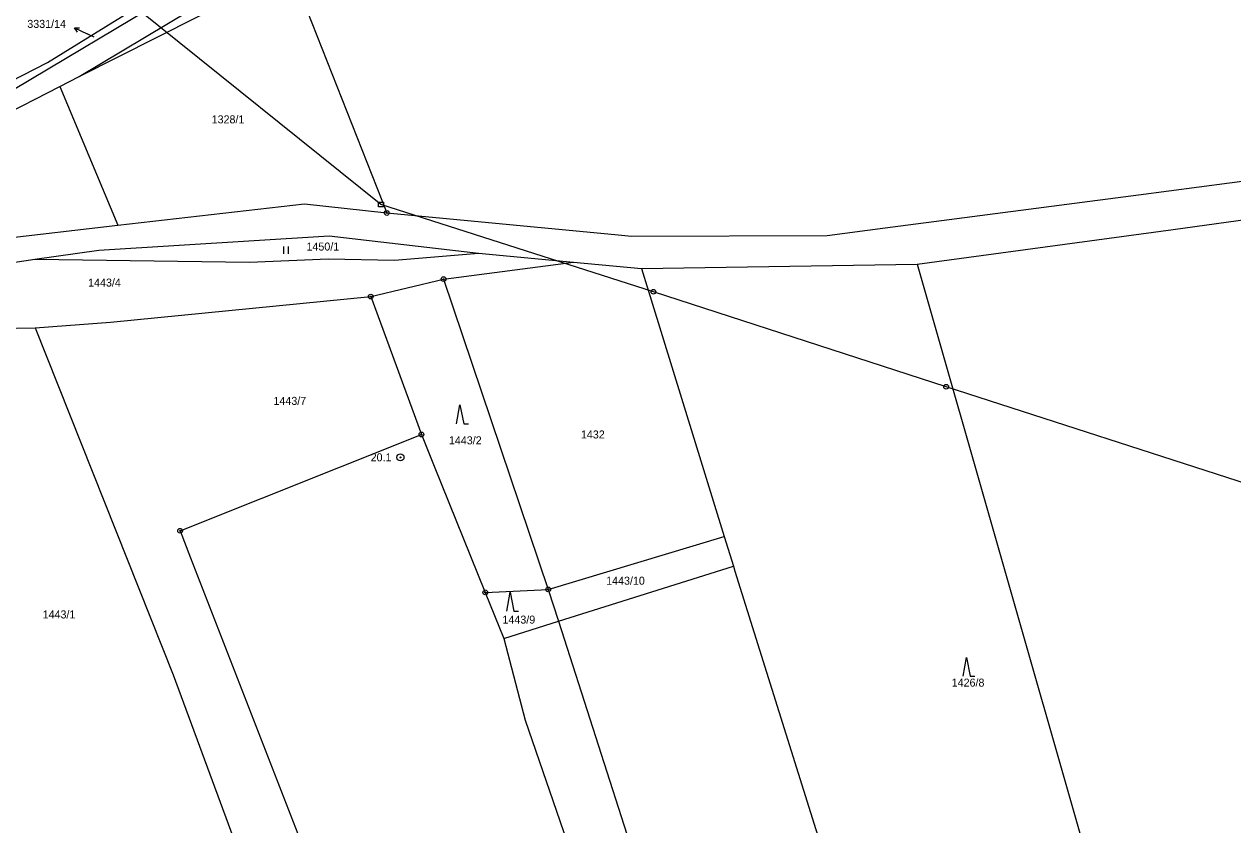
# Model space of a CAD drawing. Extents: x -763205 to -760228, y -1155311 to -1152844.
# Drawn here: x -761010 to -760753.2, y -1154938.5 to -1154768.5 of the extents above; entities that cross this region are included whole.
import ezdxf

# ---------------------------------------------------------------- set-up
doc = ezdxf.new("R2010")
doc.units = 0
for name, color, linetype in [('Vrstva 1', 7, 'Continuous'), ('Vrstva 12', 7, 'Continuous'), ('Vrstva 16', 7, 'Continuous'), ('Vrstva 17', 7, 'Continuous'), ('Vrstva 18', 7, 'Continuous'), ('Vrstva 24', 7, 'Continuous'), ('Vrstva 25', 7, 'Continuous'), ('Vrstva 26', 7, 'Continuous'), ('Vrstva 6', 7, 'Continuous')]:
    doc.layers.add(name, color=color, linetype=linetype)

msp = doc.modelspace()

# ---------------------------------------------------------------- linework, layer by layer
at = {"layer": 'Vrstva 1'}
for p, q in [((-761004.98, -1154776.68), (-760973.16, -1154756.96)), ((-760998.25, -1154779.61), (-760953.29, -1154756.91)), ((-760953.29, -1154756.91), (-760932.94, -1154808.61)), ((-761012.89, -1154780.69), (-761004.98, -1154776.68)), ((-761002.36, -1154781.72), (-760998.25, -1154779.61)), ((-761079.75, -1154821.46), (-761002.36, -1154781.72)), ((-760773.29, -1154804.72), (-760744.44, -1154800.93)), ((-760990.06, -1154811.21), (-760950.4, -1154806.68)), ((-760950.4, -1154806.68), (-760932.94, -1154808.61)), ((-760827.1, -1154811.79), (-760773.29, -1154804.72)), ((-760932.94, -1154808.61), (-760884.5, -1154813.19)), ((-760765.94, -1154812.1), (-760737.59, -1154808.24)), ((-761079.75, -1154821.46), (-760990.06, -1154811.21)), ((-760839.38, -1154813.4), (-760827.1, -1154811.79)), ((-760820.27, -1154819.5), (-760765.94, -1154812.1)), ((-760994.13, -1154816.52), (-760945.18, -1154813.44)), ((-760945.18, -1154813.44), (-760913.48, -1154817.12)), ((-760884.5, -1154813.19), (-760880.95, -1154813.53)), ((-760880.95, -1154813.53), (-760839.38, -1154813.4)), ((-761007.69, -1154818.44), (-760994.13, -1154816.52)), ((-760931.28, -1154818.64), (-760913.48, -1154817.12)), ((-760913.48, -1154817.12), (-760893.27, -1154819.05)), ((-761061.06, -1154826.5), (-761007.69, -1154818.44)), ((-761007.69, -1154818.44), (-760962.11, -1154819.03)), ((-760962.11, -1154819.03), (-760945.41, -1154818.34)), ((-760945.41, -1154818.34), (-760931.28, -1154818.64)), ((-760893.27, -1154819.05), (-760878.84, -1154820.42)), ((-760878.84, -1154820.42), (-760820.27, -1154819.5)), ((-760820.27, -1154819.5), (-760754.43, -1155049.79)), ((-760878.84, -1154820.42), (-760861.27, -1154877.3)), ((-760936.35, -1154826.36), (-760920.88, -1154822.66)), ((-760920.88, -1154822.66), (-760898.66, -1154888.55)), ((-760936.35, -1154826.36), (-760925.58, -1154855.65)), ((-760976.85, -1154876.1), (-760925.58, -1154855.65)), ((-760925.58, -1154855.65), (-760922.86, -1154862.37)), ((-760922.86, -1154862.37), (-760912.02, -1154889.17)), ((-760976.85, -1154876.1), (-760974.63, -1154881.81)), ((-760861.27, -1154877.3), (-760859.33, -1154883.59)), ((-760974.63, -1154881.81), (-760942.59, -1154964.12)), ((-760896.45, -1154895.28), (-760859.33, -1154883.59)), ((-760912.02, -1154889.17), (-760898.66, -1154888.55)), ((-760912.02, -1154889.17), (-760908.06, -1154898.94)), ((-760908.06, -1154898.94), (-760896.45, -1154895.28))]:
    msp.add_line(p, q, dxfattribs=at)
at = {"layer": 'Vrstva 12'}
for p, q in [((-760934.17, -1154806.8), (-760985.64, -1154765.47)), ((-760876.31, -1154825.34), (-760934.17, -1154806.8)), ((-760814.13, -1154845.52), (-760876.31, -1154825.34)), ((-760723.38, -1154874.86), (-760814.13, -1154845.52))]:
    msp.add_line(p, q, dxfattribs=at)
at = {"layer": 'Vrstva 16'}
for p in [(-760999.303, -1154769.302), (-760995.06, -1154771.26)]:
    msp.add_line(p, (-760996.58, -1154770.56), dxfattribs=at)
msp.add_lwpolyline([(-760998.605, -1154770.175), (-760999.303, -1154769.302), (-760998.186, -1154769.267)], dxfattribs=at)
at = {"layer": 'Vrstva 24'}
for centre, radius in [((-760932.94, -1154808.61), 0.5), ((-760932.94, -1154808.61), 0.1), ((-760920.88, -1154822.66), 0.5), ((-760920.88, -1154822.66), 0.1), ((-760936.35, -1154826.36), 0.5), ((-760936.35, -1154826.36), 0.1), ((-760925.58, -1154855.65), 0.5), ((-760925.58, -1154855.65), 0.1), ((-760930.04, -1154860.5), 0.75), ((-760930.04, -1154860.5), 0.1), ((-760976.85, -1154876.1), 0.5), ((-760976.85, -1154876.1), 0.1), ((-760912.02, -1154889.17), 0.5), ((-760912.02, -1154889.17), 0.1), ((-760898.66, -1154888.55), 0.5), ((-760898.66, -1154888.55), 0.1)]:
    msp.add_circle(centre, radius, dxfattribs=at)
at = {"layer": 'Vrstva 25'}
for p, q in [((-760954.8, -1154817.25), (-760954.8, -1154815.75)), ((-760953.8, -1154817.25), (-760953.8, -1154815.75))]:
    msp.add_line(p, q, dxfattribs=at)
for points in [[(-760918.1, -1154853.35), (-760917.4, -1154849.35), (-760916.6, -1154853.35), (-760915.6, -1154853.35)], [(-760907.43, -1154893.14), (-760906.73, -1154889.14), (-760905.93, -1154893.14), (-760904.93, -1154893.14)], [(-760810.53, -1154906.99), (-760809.83, -1154902.99), (-760809.03, -1154906.99), (-760808.03, -1154906.99)]]:
    msp.add_lwpolyline(points, dxfattribs=at)
at = {"layer": 'Vrstva 26'}
msp.add_lwpolyline([(-760934.67, -1154806.3), (-760933.67, -1154806.3), (-760933.67, -1154807.3), (-760934.67, -1154807.3)], close=True, dxfattribs=at)
for centre in [(-760876.31, -1154825.34), (-760814.13, -1154845.52)]:
    msp.add_circle(centre, 0.5, dxfattribs=at)
at = {"layer": 'Vrstva 6'}
for p, q in [((-761012.22, -1154782.37), (-760972.57, -1154758.7)), ((-760998.25, -1154779.61), (-760965.58, -1154760.07)), ((-761002.36, -1154781.72), (-760990.06, -1154811.21)), ((-760920.88, -1154822.66), (-760893.27, -1154819.05)), ((-760991.64, -1154831.79), (-760936.35, -1154826.36)), ((-761007.65, -1154833.01), (-760991.64, -1154831.79)), ((-761057.98, -1154833.68), (-761007.65, -1154833.01)), ((-761007.65, -1154833.01), (-760978.32, -1154906.71)), ((-760898.66, -1154888.55), (-760861.27, -1154877.3)), ((-760859.33, -1154883.59), (-760859, -1154884.65)), ((-760859, -1154884.65), (-760811.47, -1155036.07)), ((-760898.66, -1154888.55), (-760896.45, -1154895.28)), ((-760896.45, -1154895.28), (-760863.8, -1154997.1)), ((-760908.06, -1154898.94), (-760903.56, -1154916.34)), ((-760978.32, -1154906.71), (-760957.61, -1154962.77)), ((-760903.56, -1154916.34), (-760875.95, -1154996.13))]:
    msp.add_line(p, q, dxfattribs=at)

# ---------------------------------------------------------------- texts
at = {"layer": 'Vrstva 16'}
msp.add_text('3331/14', height=1.7, dxfattribs=at).set_placement((-761009.292, -1154769.3))
at = {"layer": 'Vrstva 17'}
msp.add_text('20.1', height=1.7, dxfattribs=at).set_placement((-760936.369, -1154861.35))
at = {"layer": 'Vrstva 18'}
for s, height, p in [('3331/14', 0.1, (-760995.046, -1154771.26)), ('1328/1', 1.7, (-760970.137, -1154789.58)), ('1450/1', 1.7, (-760949.997, -1154816.59)), ('1443/4', 1.7, (-760996.377, -1154824.24)), ('1443/7', 1.7, (-760957.007, -1154849.36)), ('1432', 1.7, (-760891.707, -1154856.49)), ('1443/2', 1.7, (-760919.747, -1154857.74)), ('1443/10', 1.7, (-760886.347, -1154887.55)), ('1443/1', 1.7, (-761006.037, -1154894.71)), ('1443/9', 1.7, (-760908.371, -1154895.81)), ('1426/8', 1.7, (-760812.957, -1154909.19))]:
    msp.add_text(s, height=height, dxfattribs=at).set_placement(p)

doc.saveas('drawing.dxf')
